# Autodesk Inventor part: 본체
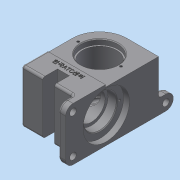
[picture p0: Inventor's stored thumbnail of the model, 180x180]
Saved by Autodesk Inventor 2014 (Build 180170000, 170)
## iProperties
Created: 2023-09
Part Number: 본체
Material: 일반
Document SubType Name: Modeling
Designer: dg
Density: 1 g/cm^3
Appearance: 기본값
Author: dg
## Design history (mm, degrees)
sketch "스케치1"
  geometry: L1 (0, 0)-(-80, 0); L2 (-80, 0)-(-80, 106); L3 (-80, 106)-(0, 106); L4 (0, 106)-(0, 0); 1 further point
  constraints: 8 end point, 2 parallel, 1 coincident, 1 horizontal, 1 perpendicular
  dimensions: "d0" = 106 distance of L3.end L1.start; "d1" = 80 distance of L2.end L3.end
extrude "돌출1" new body sketch "스케치1" distance "d2" = 72; taper "d3" = 0 deg
fillet "모깎기1" dims "d4" = 37
node "작업 평면1"
sketch "스케치3"
  geometry: L1 (-43, 106)-(0, 106) reference; L2 (0, 106)-(0, 0) reference; L3 (0, 0)-(-80, 0) reference; L4 (-80, 0)-(-80, 69) reference; L5 (-80, 35)-(0, 35); L6 (-80, 66.5)-(-77, 66.5); L7 (-77, 66.5)-(-77, 57.5); L8 (-77, 57.5)-(-65, 57.5); L9 (-65, 57.5)-(-65, 53.5); L10 (-65, 53.5)-(-20, 53.5); L11 (-20, 53.5)-(-20, 57.5); L12 (-20, 57.5)-(-8, 57.5); L13 (-8, 57.5)-(-8, 66.5); L14 (-8, 66.5)-(0, 66.5); A1 r 37 centre (-43, 69) between (-43, 106) and (-80, 69) reference
  constraints: 20 end point, 5 parallel, 4 point on line, 3 perpendicular, 2 horizontal, 2 horizontal alignment, 1 collinear
  dimensions: "d5" = 35 distance from line of L3 L5.start; "d6" = 3 distance of L6.start L6.end; "d7" = 12 distance of L7.end L8.end; "d8" = 8 distance of L13.end L14.end; "d9" = 37 diameter of L10 L5; "d10" = 45 diameter of L8 L5; "d11" = 63 diameter of L6 L5
revolve "회전1" sketch "스케치3" stored, may be unused: angle "d12" = 90 deg
sketch "스케치4"
  geometry: L1 (-80, 0)-(0, 0) reference; L2 (0, 0)-(0, 106) reference; L3 (-51, 0)-(-35, 0); L4 (-35, 0)-(-35, 20); L5 (-35, 20)-(-51, 20); L6 (-51, 20)-(-51, 0); 1 further point
  constraints: 8 end point, 2 parallel, 1 horizontal, 1 midpoint, 1 perpendicular, 1 point on line
  dimensions: "d13" = 16 distance of L4.end L5.end; "d14" = 20 distance of L5.end L3.start; "d15" = 43 distance from line of point (-43, 20) L2
extrude "돌출2" cut sketch "스케치4" stored distance "d16" = 72; taper "d17" = 0 deg
sketch "스케치5"
  geometry: L1 (-72, 0)-(0, 0); L2 (0, 0)-(0, -20); L3 (0, -20)-(-72, -20); L4 (-72, -20)-(-72, 0); 1 further point
  constraints: 8 end point, 2 parallel, 1 horizontal, 1 perpendicular, 1 vertical alignment
  dimensions: "d18" = 20 distance of L1.end L2.end
extrude "돌출3" join sketch "스케치5" distance "d19" = 10; taper "d20" = 0 deg
sketch "스케치6"
  geometry: L1 (0, 0)-(0, -20) reference; L2 (0, -20)-(72, -20) reference; 2 further points
  constraints: 1 horizontal alignment
  dimensions: "d21" = 52 distance of point (62, -10) point (10, -10); "d22" = 10 distance from line of L1 point (10, -10); "d23" = 10 distance from line of L2 point (10, -10)
hole "구멍1" sketch "스케치6" at (10, -10), (62, -10) diameter "d24" = 9; stored, may be unused: countersink angle "d28" = 90 deg, drill point angle "d30" = 118 deg; dims "d25" = 6, "d26" = 4, "d27" = 2, "d29" = 8
fillet "모깎기2" dims "d31" = 10
node "작업 평면2"
node "작업 평면3"
sketch "스케치12"
  geometry: L1 (0, 0)-(52, 0) reference; L2 (62, 126)-(-10, 126) reference; L3 (62, 126)-(62, 136); L4 (42, 136)-(42, 126); A1 r 10 centre (52, 136) between (62, 136) and (42, 136); 3 further points
  constraints: 4 end point, 2 perpendicular, 2 point on circle, 2 tangent, 1 centre point, 1 coincident, 1 point on line
  dimensions: "d55" = 10 radius of A1; "d56" = 146 dimension on A1 L1
extrude "돌출5" join sketch "스케치12" distance "d57" = 10; taper "d58" = 0 deg
hole "구멍2" sketch "스케치12" diameter "d59" = 9; stored, may be unused: countersink angle "d63" = 90 deg, drill point angle "d65" = 118 deg; dims "d60" = 6, "d61" = 4, "d62" = 2, "d64" = 8
sketch "스케치13"
  geometry: C1 r 31.5 at (0, 0) reference; 2 further points
  constraints: 1 vertical alignment
  dimensions: "d66" = 26 distance of C1.centre point (0, 26)
hole "구멍3" sketch "스케치13" at (0, 26) diameter "d67" = 3.242; stored, may be unused: countersink angle "d71" = 90 deg, drill point angle "d73" = 118 deg; dims "d68" = 8, "d69" = 4, "d70" = 2, "d72" = 10
sketch "스케치14"
  geometry: C1 r 22.5 at (0, 0) reference; 2 further points
  constraints: 1 vertical alignment
  dimensions: "d77" = 26 distance of C1.centre point (0, 26)
hole "구멍4" sketch "스케치14" at (0, 26) diameter "d78" = 3.242; stored, may be unused: countersink angle "d82" = 90 deg, drill point angle "d84" = 118 deg; dims "d79" = 8, "d80" = 4, "d81" = 2, "d83" = 10
node "작업 평면4"
sketch "스케치15"
  geometry: L1 (15.172, 40)-(-10, 40) reference; L2 (-10, 40)-(-10, 126) reference; L3 (-10, 126)-(62, 126) reference; L4 (62, 126)-(62, 40) reference; L5 (62, 40)-(36.828, 40) reference; L6 (-10, 89)-(62, 89); L7 (-10, 114)-(0, 114); L8 (0, 114)-(0, 112); L9 (0, 112)-(40, 112); L10 (40, 112)-(40, 106.5); L11 (40, 106.5)-(55, 106.5); L12 (55, 106.5)-(55, 104.5); L13 (55, 104.5)-(59, 104.5); L14 (59, 104.5)-(59, 89); A1 r 18.5 centre (26, 55) between (36.828, 40) and (15.172, 40) reference; 1 further point
  constraints: 18 end point, 8 parallel, 4 point on line, 1 perpendicular
  dimensions: "d86" = 34 distance from line of A1.centre L6; "d87" = 10 distance of L7.start L7.end; "d88" = 40 distance of L8.end L9.end; "d89" = 15 distance of L10.end L11.end; "d90" = 4 distance of L12.end L13.end; "d91" = 50 diameter of L7 L6; "d92" = 46 diameter of L9 L6; "d93" = 35 diameter of L11 L6; "d94" = 31 diameter of L13 L6
revolve "회전4" sketch "스케치15" stored, may be unused: angle "d95" = 90 deg
sketch "스케치16"
  geometry: L1 (0, 106)-(-43, 106) reference; L2 (-43, 106)-(0, 106) reference; L3 (0, 106)-(0, -10) reference; L4 (0, -10)-(-10, -10) reference; L5 (-10, -10)-(-10, 0) reference; L6 (-10, 0)-(-35, 0) reference; L7 (-35, 0)-(-35, 20) reference; L8 (-35, 20)-(-51, 20) reference; L9 (-51, 20)-(-51, 0) reference; L10 (-51, 0)-(-80, 0) reference; L11 (-80, 0)-(-80, 69) reference; L12 (-80, 34)-(0, 34); C1 r 25 at (-43, 69) reference; C2 r 25 at (-43, 69) reference; A1 r 37 centre (-43, 69) between (-43, 106) and (-80, 69) reference; 1 further point
  constraints: 2 end point, 2 point on line, 1 perpendicular
  dimensions: "d99" = 72 distance between parallel lines of L12 L1
extrude "돌출6" cut sketch "스케치16" distance "d100" = 3; taper "d101" = 0 deg
sketch "스케치17"
  geometry: C1 r 25 at (-43, 69) reference; 2 further points
  constraints: 1 horizontal alignment
  dimensions: "d102" = 29 distance of point (-14, 69) C1.centre
hole "구멍5" sketch "스케치17" at (-14, 69) diameter "d103" = 3.242; stored, may be unused: countersink angle "d107" = 90 deg, drill point angle "d109" = 118 deg; dims "d104" = 8, "d105" = 4, "d106" = 2, "d108" = 10
sketch "스케치18"
  geometry: L1 (-80, 0)-(-51, 0) reference; C1 r 15.5 at (-43, 69) reference; 2 further points
  constraints: 1 vertical alignment, 1 other
  dimensions: "d113" = 27 distance from line of L1 point (-43, 27)
feature "엠보싱1" sketch "스케치18" dims "d114" = 0.5, "d115" = 0
chamfer "모따기1" distance "d116" = 1; stored, may be unused: second distance "d117" = 2, angle "d118" = 45 deg
fillet "모깎기3" dims "d119" = 0.3
fillet "모깎기4" dims "d120" = 3
fillet "모깎기5" dims "d121" = 3
fillet "모깎기6" dims "d122" = 3
fillet "모깎기7" dims "d123" = 3
fillet "모깎기8" dims "d124" = 3
sketch "스케치19"
  geometry: L1 (51, -10)-(51, -62) reference; L2 (15.007, -50)-(0.993, -50) reference; L3 (31, -10)-(-15, -10) reference; L4 (-14, -13.5)-(-14, -58.5) reference; L5 (-25, -58.5)-(-25, -13.5) reference; L6 (16, -72)-(0, -72) reference; 3 further points
  constraints: 1 horizontal alignment, 1 vertical alignment
  dimensions: "d125" = 43 distance from line of L1 point (8, -11); "d126" = 50 distance of point (8, -61) point (8, -11); "d127" = 11 distance from line of L6 point (8, -61)
hole "구멍6" sketch "스케치19" at (8, -11), (8, -61) diameter "d128" = 3.242; stored, may be unused: countersink angle "d132" = 82 deg, drill point angle "d134" = 118 deg; dims "d129" = 8, "d130" = 3.023, "d131" = 2, "d133" = 10
node "솔리드1"
pattern_circular "원형 패턴1" dims angle "d75" = 360 deg
pattern_circular "원형 패턴2" dims angle "d97" = 360 deg
pattern_circular "원형 패턴3" dims angle "d111" = 360 deg
node "투영된 루프1"
node "투영된 루프2"
node "절단 모서리 투영1"
node "절단 모서리 투영5"
node "절단 모서리 투영6"
other parameters: "d85" = -43
